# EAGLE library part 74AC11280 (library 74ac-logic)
9-bit PARITY GENERATOR/CHECKER
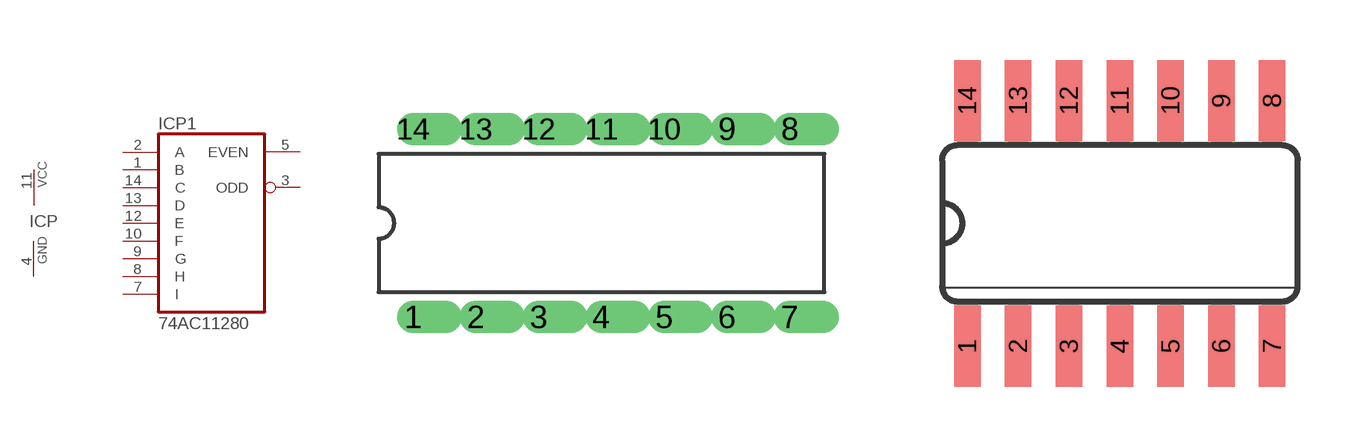
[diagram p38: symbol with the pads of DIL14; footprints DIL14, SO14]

Designator prefix IC; gates P=PWRN P1=7411280

## 74AC11280  [DIL14]
1  P1:B  in
2  P1:A  in
3  P1:ODD  out
4  P:GND  pwr
5  P1:EVEN  out
7  P1:I  in
8  P1:H  in
9  P1:G  in
10  P1:F  in
11  P:VCC  pwr
12  P1:E  in
13  P1:D  in
14  P1:C  in

## 74AC11280D  [SO14]
Pads as for DIL14

## Footprint DIL14 (pad centres in mm)
Dual In Line
drill 0.813 offset: 1 -7.62,-3.81; 2 -5.08,-3.81; 3 -2.54,-3.81; 4 0,-3.81; 5 2.54,-3.81; 6 5.08,-3.81; 7 7.62,-3.81; 8 7.62,3.81; 9 5.08,3.81; 10 2.54,3.81; 11 0,3.81; 12 -2.54,3.81; 13 -5.08,3.81; 14 -7.62,3.81

## Footprint SO14 (pad centres in mm)
Small Outline package 150 mil
smd 0.66 x 2.032: 1 -3.81,-3.073; 2 -2.54,-3.073; 3 -1.27,-3.073; 4 0,-3.073; 5 1.27,-3.073; 6 2.54,-3.073; 7 3.81,-3.073; 8 3.81,3.073; 9 2.54,3.073; 10 1.27,3.073; 11 0,3.073; 12 -1.27,3.073; 13 -2.54,3.073; 14 -3.81,3.073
